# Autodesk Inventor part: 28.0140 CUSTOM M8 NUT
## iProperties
Created: 2012-04
Part Number: 28.0140 CUSTOM M8 NUT
Material: Steel
Document SubType Name: Modeling
Designer: Administrator
Mass: 8.33225 g
Surface Area: 9.18102 cm^2
Volume: 1.06143 cm^3
Density: 7.85 g/cm^3
Author: Administrator
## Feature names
1. Extrusion1
2. Hole1
3. Extrusion2
4. Mirror1
